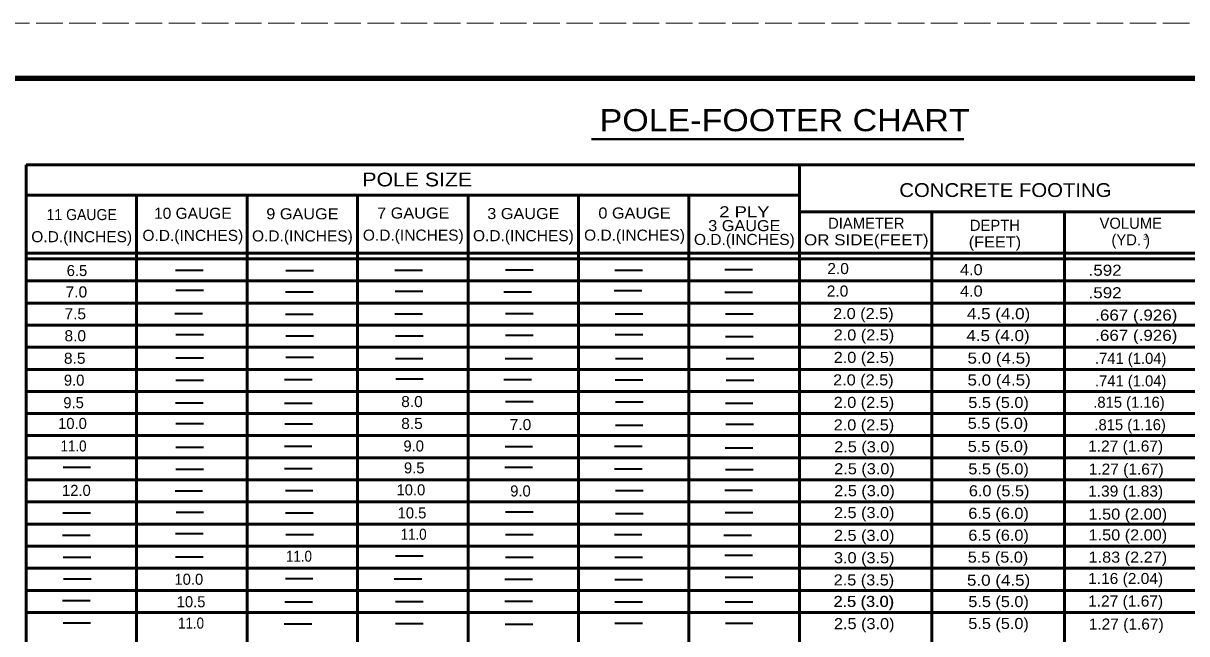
# Model space of a CAD drawing. Extents: x -560 to 120, y 26 to 466.
# Drawn here: x -268.1 to -57.5, y 355.4 to 465.8 of the extents above; entities that cross this region are included whole.
import ezdxf
from ezdxf.enums import TextEntityAlignment as Align

# ---------------------------------------------------------------- set-up
doc = ezdxf.new("R2010")
doc.units = 0
doc.header["$LTSCALE"] = 0.8
doc.linetypes.add('LONG_DASHED', pattern=[7.5, 6, -1.5])
doc.layers.add('1', color=7, linetype='Continuous', lineweight=53)
doc.layers.add('61', color=7, linetype='Continuous', lineweight=35)

msp = doc.modelspace()

# ---------------------------------------------------------------- linework, layer by layer
at = {"layer": '1', "lineweight": 40}
msp.add_line((-165.2601, 444.8533), (-97.8363, 444.8533), dxfattribs=at)
at = {"layer": '1'}
for p, q in [((-267.5954, 440.21), (-267.5954, 267.21)), ((-267.5954, 440.21), (-118.7124, 440.21)), ((-127.5954, 440.21), (-127.5954, 267.21)), ((-127.5876, 440.21), (-7.5954, 440.21)), ((-267.5954, 434.71), (-127.5954, 434.71)), ((-247.5954, 434.71), (-247.5954, 267.21)), ((-227.5954, 434.71), (-227.5954, 267.21)), ((-207.5954, 434.71), (-207.5954, 434.6408)), ((-207.5954, 434.71), (-207.5954, 267.21)), ((-187.5954, 434.71), (-187.5954, 267.21)), ((-167.5954, 434.71), (-167.5954, 434.6408)), ((-167.5954, 434.71), (-167.5954, 267.21)), ((-147.5954, 434.71), (-147.5954, 267.21)), ((-127.5954, 431.71), (-7.5954, 431.71)), ((-103.5954, 431.71), (-103.5954, 267.21)), ((-79.5954, 431.71), (-79.5954, 267.21)), ((-267.5954, 424.21), (-7.6086, 424.21)), ((-267.5954, 423.21), (-7.6086, 423.21)), ((-267.5954, 419.21), (-7.6086, 419.21)), ((-267.5954, 415.21), (-7.6086, 415.21)), ((-267.5954, 411.21), (-7.6086, 411.21)), ((-267.5954, 407.21), (-7.6086, 407.21)), ((-267.5954, 403.21), (-7.6086, 403.21)), ((-267.5954, 399.21), (-7.6086, 399.21)), ((-267.5954, 395.21), (-7.6086, 395.21)), ((-267.5954, 391.21), (-7.6086, 391.21)), ((-267.5954, 387.21), (-7.6086, 387.21)), ((-267.5954, 383.21), (-7.6086, 383.21)), ((-267.5954, 379.21), (-7.6086, 379.21)), ((-267.5954, 375.21), (-7.6086, 375.21)), ((-267.5954, 371.21), (-7.6086, 371.21)), ((-267.5954, 367.21), (-7.6086, 367.21)), ((-267.5954, 363.21), (-7.6086, 363.21)), ((-267.5954, 359.21), (-7.6086, 359.21))]:
    msp.add_line(p, q, dxfattribs=at)
at = {"layer": '1', "lineweight": 35}
for p, q in [((-240.5342, 421.1797), (-235.5342, 421.1797)), ((-220.5896, 421.1281), (-215.5896, 421.1281)), ((-200.8459, 421.1797), (-195.8459, 421.1797)), ((-180.7983, 421.2312), (-175.7983, 421.2312)), ((-161.0031, 421.1797), (-156.0031, 421.1797)), ((-141.0803, 421.2557), (-136.0803, 421.2557)), ((-240.5097, 417.5159), (-235.5097, 417.5159)), ((-220.6167, 417.2608), (-215.6167, 417.2608)), ((-200.7699, 417.3368), (-195.7699, 417.3368)), ((-181.1023, 417.2635), (-176.1023, 417.2635)), ((-161.128, 417.4915), (-156.128, 417.4915)), ((-141.0803, 417.1848), (-136.0803, 417.1848)), ((-240.6887, 413.3174), (-235.6887, 413.3174)), ((-220.6167, 413.1655), (-215.6167, 413.1655)), ((-200.846, 413.2415), (-195.846, 413.2415)), ((-180.7983, 413.3446), (-175.7983, 413.3446)), ((-160.976, 413.2659), (-155.976, 413.2659)), ((-140.9799, 413.2415), (-135.9799, 413.2415)), ((-240.5097, 409.5017), (-235.5097, 409.5017)), ((-220.5652, 409.2982), (-215.5652, 409.2982)), ((-200.694, 409.2982), (-195.694, 409.2982)), ((-180.8227, 409.3742), (-175.8227, 409.3742)), ((-160.9733, 409.5017), (-155.9733, 409.5017)), ((-140.9799, 409.1435), (-135.9799, 409.1435)), ((-240.5097, 405.3033), (-235.5097, 405.3033)), ((-220.5896, 405.4308), (-215.5896, 405.4308)), ((-200.7455, 405.1757), (-195.7455, 405.1757)), ((-180.8988, 405.1514), (-175.8988, 405.1514)), ((-160.9244, 405.1757), (-155.9244, 405.1757)), ((-140.8794, 405.1757), (-135.8794, 405.1757)), ((-240.4852, 401.2325), (-235.4852, 401.2325)), ((-220.8176, 401.3601), (-215.8176, 401.3601)), ((-200.6939, 401.512), (-195.6939, 401.512)), ((-181.1022, 401.3601), (-176.1022, 401.3601)), ((-160.9516, 401.284), (-155.9516, 401.284)), ((-140.8794, 401.2569), (-135.8794, 401.2569)), ((-240.5368, 397.1616), (-235.5368, 397.1616)), ((-220.8176, 397.0857), (-215.8176, 397.0857)), ((-180.7957, 397.3652), (-175.7957, 397.3652)), ((-160.8729, 397.3408), (-155.8729, 397.3408)), ((-141.0043, 397.1101), (-136.0043, 397.1101)), ((-240.4852, 393.4218), (-235.4852, 393.4218)), ((-220.7417, 393.3458), (-215.7417, 393.3458)), ((-160.9243, 393.1152), (-155.9243, 393.1152)), ((-140.9038, 393.2943), (-135.9038, 393.2943)), ((-240.4852, 389.0959), (-235.4852, 389.0959)), ((-220.8448, 389.3264), (-215.8448, 389.3264)), ((-180.8961, 389.2234), (-175.8961, 389.2234)), ((-161.0792, 389.2994), (-156.0792, 389.2994)), ((-141.0313, 388.9928), (-136.0313, 388.9928)), ((-260.9129, 385.4837), (-255.9129, 385.4837)), ((-180.9476, 385.4837), (-175.9476, 385.4837)), ((-240.4852, 385.1526), (-235.4852, 385.1526)), ((-220.7932, 385.2802), (-215.7932, 385.2802)), ((-161.0519, 385.2286), (-156.0519, 385.2286)), ((-140.9798, 385.0767), (-135.9798, 385.0767)), ((-220.6656, 381.2852), (-215.6656, 381.2852)), ((-160.8756, 381.2852), (-155.8756, 381.2852)), ((-141.1074, 381.3368), (-136.1074, 381.3368)), ((-240.6373, 381.2093), (-235.6373, 381.2093)), ((-260.94, 377.2144), (-255.94, 377.2144)), ((-240.4582, 377.342), (-235.4582, 377.342)), ((-220.6412, 377.2388), (-215.6412, 377.2388)), ((-180.82, 377.4179), (-175.82, 377.4179)), ((-160.8755, 377.1384), (-155.8755, 377.1384)), ((-141.0314, 377.2905), (-136.0314, 377.2905)), ((-260.9915, 373.2195), (-255.9915, 373.2195)), ((-240.5367, 373.4746), (-235.5367, 373.4746)), ((-220.5652, 373.3471), (-215.5652, 373.3471)), ((-180.7956, 373.3471), (-175.7956, 373.3471)), ((-161.1035, 373.3471), (-156.1035, 373.3471)), ((-141.2594, 373.1951), (-136.2594, 373.1951)), ((-260.8912, 369.2246), (-255.8912, 369.2246)), ((-240.5368, 369.2763), (-235.5368, 369.2763)), ((-200.7429, 369.4797), (-195.7429, 369.4797)), ((-180.8227, 369.2247), (-175.8227, 369.2247)), ((-161.0031, 369.2002), (-156.0031, 369.2002)), ((-141.1074, 369.6073), (-136.1074, 369.6073)), ((-260.8396, 365.3084), (-255.8396, 365.3084)), ((-220.6656, 365.3329), (-215.6656, 365.3329)), ((-200.9463, 365.3085), (-195.9463, 365.3085)), ((-180.9502, 365.2053), (-175.9502, 365.2053)), ((-161.0004, 365.1538), (-156.0004, 365.1538)), ((-141.0558, 365.6125), (-136.0558, 365.6125)), ((-260.9915, 361.3896), (-255.9915, 361.3896)), ((-220.766, 361.1345), (-215.766, 361.1345)), ((-200.7428, 361.2106), (-195.7428, 361.2106)), ((-180.9503, 361.262), (-175.9503, 361.262)), ((-161.0031, 361.1589), (-156.0031, 361.1589)), ((-141.0586, 361.159), (-136.0586, 361.159)), ((-260.9156, 357.3187), (-255.9156, 357.3187)), ((-220.8936, 357.1396), (-215.8936, 357.1396)), ((-200.7184, 357.2157), (-195.7184, 357.2157)), ((-180.8743, 357.0637), (-175.8743, 357.0637)), ((-161.0031, 357.2645), (-156.0031, 357.2645)), ((-141.0069, 357.2917), (-136.0069, 357.2917))]:
    msp.add_line(p, q, dxfattribs=at)
at = {"layer": '61', "linetype": 'LONG_DASHED', "lineweight": 13}
msp.add_line((-559.7809, 465.8427), (120.2391, 465.8427), dxfattribs=at)
at = {"layer": '61', "lineweight": 158}
msp.add_lwpolyline([(109.2591, 455.8427), (-529.7809, 455.8427), (-529.7809, 35.8227)], dxfattribs=at)

# ---------------------------------------------------------------- texts
at = {"layer": '1'}
for s, height, width, p in [('POLE-FOOTER CHART', 4, 1.15, (-163.766, 446.3082)), ('POLE SIZE', 2.5, 1.15, (-206.7212, 436.3185)), ('CONCRETE FOOTING', 2.5, 1.1, (-109.5113, 434.4046))]:
    msp.add_text(s, height=height, dxfattribs=dict(at, width=width)).set_placement(p)
for s, height, width, p in [('11 GAUGE', 2, 0.95, (-257.537, 430.2189)), ('10 GAUGE', 2, 1.05, (-237.4175, 430.4518)), ('9 GAUGE', 2, 1.1, (-217.5776, 430.3587)), ('7 GAUGE', 2, 1.1, (-197.5048, 430.4984)), ('3 GAUGE', 2, 1.1, (-177.5717, 430.4052)), ('0 GAUGE', 2, 1.1, (-157.4523, 430.4984)), ('2 PLY', 2, 1.25, (-137.5657, 430.7205)), ('3 GAUGE', 2, 1.1, (-137.5657, 428.2205)), ('O.D.(INCHES)', 2, 1.05, (-257.537, 426.2189)), ('O.D.(INCHES)', 2, 1.05, (-237.4175, 426.4518)), ('O.D.(INCHES)', 2, 1.05, (-217.5776, 426.3587)), ('O.D.(INCHES)', 2, 1.05, (-197.5049, 426.4984)), ('O.D.(INCHES)', 2, 1.05, (-177.5718, 426.4052)), ('O.D.(INCHES)', 2, 1.05, (-157.4524, 426.4984)), ('O.D.(INCHES)', 2, 1.05, (-137.5657, 425.7205)), ('OR SIDE(FEET)', 2, 1.15, (-115.4904, 425.65)), ('3', 1, 0.9, (-65.0055, 426.6254)), ('(FEET)', 2, 1.1, (-92.204, 425.2774)), ('2.0', 2, 1.05, (-120.5962, 420.4527)), ('4.0', 2, 1.1, (-96.4765, 420.2491)), ('.592', 2, 1.15, (-72.255, 420.1474)), ('7.0', 2, 1.05, (-258.496, 416.2264)), ('2.0', 2, 1.05, (-120.698, 416.3819)), ('4.0', 2, 1.1, (-96.4765, 416.3819)), ('.592', 2, 1.15, (-72.255, 416.0766)), ('7.5', 2, 1.05, (-258.6995, 412.2573)), ('2.0 (2.5)', 2, 1.1, (-116.0167, 412.311)), ('4.5 (4.0)', 2, 1.15, (-91.5405, 412.2877)), ('.667 (.926)', 2, 1.15, (-66.6065, 412.0345)), ('8.0', 2, 1.05, (-258.6996, 408.2883)), ('2.0 (2.5)', 2, 1.1, (-115.9147, 408.4437)), ('4.5 (4.0)', 2, 1.15, (-91.6422, 408.3186)), ('.667 (.926)', 2, 1.15, (-66.6065, 408.3707)), ('8.5', 2, 1.05, (-258.8013, 404.2174)), ('2.0 (2.5)', 2, 1.1, (-115.9148, 404.3729)), ('5.0 (4.5)', 2, 1.15, (-91.4388, 404.2477)), ('2.0 (2.5)', 2, 1.1, (-116.0166, 400.302)), ('5.0 (4.5)', 2, 1.15, (-91.4388, 400.2787)), ('8.0', 2, 1.05, (-197.7387, 396.3815)), ('2.0 (2.5)', 2, 1.1, (-115.9148, 396.2312)), ('5.5 (5.0)', 2, 1.1, (-91.5406, 396.2077)), ('8.5', 2, 1.05, (-197.7387, 392.4125)), ('7.0', 2, 1.05, (-178.0969, 392.2103)), ('2.0 (2.5)', 2, 1.1, (-115.9148, 392.1603)), ('5.5 (5.0)', 2, 1.1, (-91.6423, 392.4423)), ('11.0', 2, 0.9, (-259.0049, 388.3412)), ('2.5 (3.0)', 2, 1.1, (-115.813, 388.1913)), ('5.5 (5.0)', 2, 1.1, (-91.6423, 388.2697)), ('1.27 (1.67)', 2, 1.05, (-68.5401, 388.3217)), ('2.5 (3.0)', 2, 1.1, (-115.813, 384.2222)), ('5.5 (5.0)', 2, 1.1, (-91.5406, 384.1988)), ('1.27 (1.67)', 2, 1.05, (-68.4384, 384.149)), ('2.5 (3.0)', 2, 1.1, (-115.813, 380.2532)), ('6.0 (5.5)', 2, 1.1, (-91.4387, 380.2297)), ('1.39 (1.83)', 2, 1.05, (-68.5401, 380.18)), ('2.5 (3.0)', 2, 1.1, (-115.8639, 376.2841)), ('6.5 (6.0)', 2, 1.1, (-91.5405, 376.1588)), ('1.50 (2.00)', 2, 1.1, (-68.1331, 376.0074)), ('11.0', 2, 0.9, (-197.4334, 372.3636)), ('2.5 (3.0)', 2, 1.1, (-115.8639, 372.1623)), ('6.5 (6.0)', 2, 1.1, (-91.5405, 372.1898)), ('1.50 (2.00)', 2, 1.1, (-68.1331, 372.2419)), ('11.0', 2, 0.9, (-218.1947, 368.3945)), ('3.0 (3.5)', 2, 1.1, (-115.8639, 368.1174)), ('5.5 (5.0)', 2, 1.1, (-91.6423, 368.2208)), ('1.83 (2.27)', 2, 1.1, (-68.1332, 368.2221)), ('2.5 (3.5)', 2, 1.1, (-115.9148, 364.0975)), ('5.0 (4.5)', 2, 1.15, (-91.5406, 364.048)), ('1.16 (2.04)', 2, 1.05, (-68.5401, 364.3548)), ('2.5 (3.0)', 2, 1.1, (-115.9657, 360.2043)), ('2.5 (3.0)', 2, 1.1, (-115.9148, 360.2043)), ('1.27 (1.67)', 2, 1.05, (-68.5401, 360.2839)), ('5.5 (5.0)', 2, 1.1, (-91.5406, 360.1807)), ('11.0', 2, 0.9, (-237.7347, 356.2837)), ('2.5 (3.0)', 2, 1.1, (-115.8641, 356.1842)), ('5.5 (5.0)', 2, 1.1, (-91.5406, 356.2117)), ('1.27 (1.67)', 2, 1.05, (-68.4384, 356.1112))]:
    msp.add_text(s, height=height, dxfattribs=dict(at, width=width)).set_placement(p, align=Align.CENTER)
for s, p in [('DIAMETER', (-115.4904, 428.65)), ('DEPTH', (-92.2039, 428.2774)), ('VOLUME', (-67.6136, 428.65)), ('(YD. )', (-67.6136, 425.65)), ('6.5', (-258.3942, 420.0938)), ('.741 (1.04)', (-67.6243, 404.1981)), ('9.0', (-258.9032, 400.2483)), ('.741 (1.04)', (-67.6243, 400.1273)), ('9.5', (-259.0049, 396.1775)), ('.815 (1.16)', (-67.9296, 396.2599)), ('10.0', (-259.2084, 392.412)), ('.815 (1.16)', (-67.7261, 392.189)), ('9.0', (-197.4334, 388.3417)), ('9.5', (-197.3316, 384.3726)), ('12.0', (-258.4961, 380.3012)), ('10.0', (-197.9423, 380.4035)), ('9.0', (-178.0969, 380.2013)), ('10.5', (-197.7387, 376.2309)), ('10.0', (-238.1418, 364.2219)), ('10.5', (-237.7347, 360.1511))]:
    msp.add_text(s, height=2, dxfattribs=at).set_placement(p, align=Align.CENTER)

doc.saveas('drawing.dxf')
